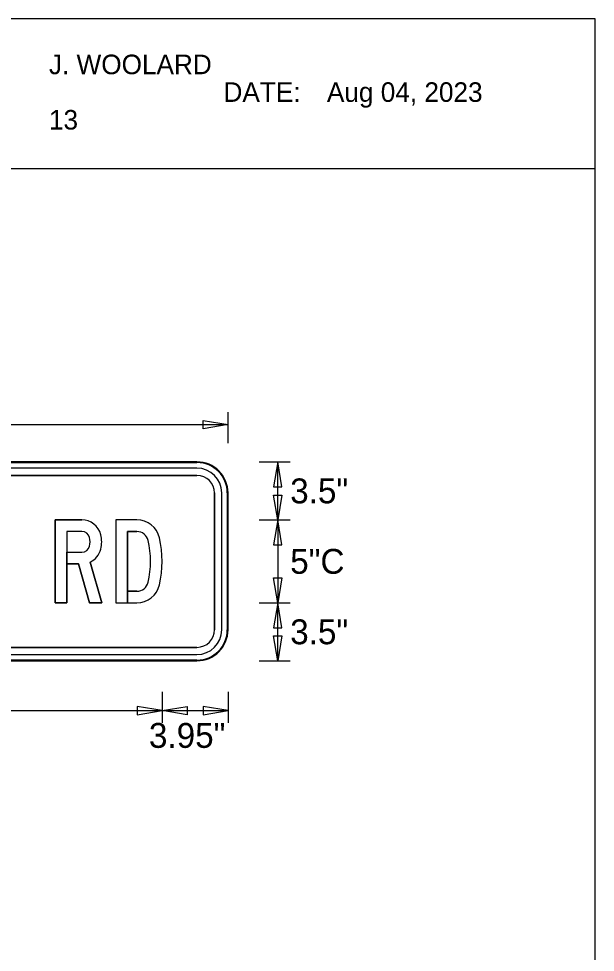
# Model space of a CAD drawing. Extents: x 57.2 to 85.4, y 153.3 to 173.4.
# Drawn here: x 66.811 to 69.711, y 168.405 to 173.098 of the extents above; entities that cross this region are included whole.
import ezdxf

# ---------------------------------------------------------------- set-up
doc = ezdxf.new("R2010")
doc.units = 0
for name, color, linetype in [('Default', 7, 'Continuous'), ('GSBWFILL', 7, 'Continuous'), ('GSCOLORFILL', 7, 'Continuous'), ('GSDIMS', 7, 'Continuous'), ('GSOUTLINE', 7, 'Continuous')]:
    doc.layers.add(name, color=color, linetype=linetype)

msp = doc.modelspace()

# ---------------------------------------------------------------- linework, layer by layer
at = {"layer": 'Default'}
for p, q in [((69.7108, 173.0983), (57.2061, 173.0983)), ((69.7108, 163.7124), (69.7108, 173.0983)), ((63.0173, 172.3449), (69.7108, 172.3449))]:
    msp.add_line(p, q, dxfattribs=at)
at = {"layer": 'GSBWFILL'}
for p, q in [((67.7078, 170.8706), (65.0203, 170.8706)), ((67.7078, 170.8393), (65.0203, 170.8393)), ((65.0203, 170.8028), (67.7078, 170.8028)), ((67.7963, 170.7143), (67.7963, 170.0268)), ((67.8328, 170.0268), (67.8328, 170.7143)), ((67.8641, 170.0268), (67.8641, 170.7143)), ((67.1292, 170.4164), (67.1292, 170.4164)), ((67.4056, 170.2206), (67.3578, 170.2206)), ((67.7078, 169.9383), (65.0207, 169.9383)), ((65.0207, 169.9018), (67.7078, 169.9018)), ((65.0203, 169.8706), (67.7078, 169.8706))]:
    msp.add_line(p, q, dxfattribs=at)
for points in [[(67.1292, 170.5206), (67.0537, 170.5206), (67.0537, 170.1622), (66.9953, 170.1622), (66.9953, 170.5789), (67.1292, 170.5789)], [(67.4056, 170.5789), (67.2995, 170.5789), (67.2995, 170.1622), (67.3578, 170.1622), (67.3578, 170.5206), (67.4056, 170.5206)], [(67.1703, 170.3671), (67.2287, 170.1622), (67.168, 170.1622), (67.1122, 170.3581), (67.0537, 170.3581), (67.0537, 170.4164), (67.1292, 170.4164)], [(67.3578, 170.2206), (67.3578, 170.1622), (67.4056, 170.1622)]]:
    msp.add_lwpolyline(points, dxfattribs=at)
for centre, radius, start, end in [((67.7078, 170.7143), 0.1562, 0, 90), ((67.7078, 170.7143), 0.125, 0, 90), ((67.7078, 170.7143), 0.0885, 0, 90), ((67.7078, 170.0268), 0.125, 270, 0), ((67.7078, 170.0268), 0.0885, 270, 0), ((67.7078, 170.0268), 0.1562, 270, 0)]:
    msp.add_arc(centre, radius, start, end, dxfattribs=at)
for centre, major_axis, start_param, end_param in [((67.1292, 170.481), (0, 0.0979), 4.954755, 6.283185), ((67.4056, 170.4622), (0, 0.1167), 4.941184, 6.283185), ((67.1292, 170.481), (0, 0.0396), 4.954755, 6.283185), ((67.0787, 170.4685), (0, 0.15), 4.470023, 4.954755), ((67.4056, 170.4622), (0, 0.0583), 4.941184, 6.283185), ((67.0787, 170.4685), (0, 0.0917), 4.470023, 4.954755), ((67.012, 170.3706), (0, 0.4625), 4.483594, 4.941184), ((67.012, 170.3706), (0, 0.5208), 4.483594, 4.941184), ((67.1292, 170.456), (0, 0.0396), 3.141593, 4.470023), ((67.1292, 170.456), (0, 0.0979), 3.574819, 4.470023), ((67.4056, 170.2789), (0, 0.0583), 3.141593, 4.483594), ((67.4056, 170.2789), (0, 0.1167), 3.141593, 4.483594)]:
    msp.add_ellipse(centre, major_axis=major_axis, ratio=0.999994, start_param=start_param, end_param=end_param, dxfattribs=at)
at = {"layer": 'GSCOLORFILL'}
for p, q in [((67.7078, 170.8706), (65.0203, 170.8706)), ((67.7078, 170.8706), (65.0203, 170.8706)), ((65.0203, 170.8669), (67.7078, 170.8669)), ((67.7078, 170.8393), (65.0203, 170.8393)), ((65.0203, 170.8028), (67.7078, 170.8028)), ((67.7963, 170.7143), (67.7963, 170.0268)), ((67.8328, 170.0268), (67.8328, 170.7143)), ((67.8604, 170.7143), (67.8604, 170.0268)), ((67.8641, 170.0268), (67.8641, 170.7143)), ((67.8641, 170.0268), (67.8641, 170.7143)), ((67.1292, 170.4164), (67.1292, 170.4164)), ((67.4056, 170.2206), (67.3578, 170.2206)), ((67.7078, 169.9383), (65.0207, 169.9383)), ((65.0207, 169.9018), (67.7078, 169.9018)), ((65.0203, 169.8706), (67.7078, 169.8706)), ((67.7078, 169.8742), (65.0204, 169.8742)), ((65.0204, 169.8706), (67.7078, 169.8706))]:
    msp.add_line(p, q, dxfattribs=at)
for points in [[(67.1292, 170.5206), (67.0537, 170.5206), (67.0537, 170.1622), (66.9953, 170.1622), (66.9953, 170.5789), (67.1292, 170.5789)], [(67.4056, 170.5789), (67.2995, 170.5789), (67.2995, 170.1622), (67.3578, 170.1622), (67.3578, 170.5206), (67.4056, 170.5206)], [(67.1703, 170.3671), (67.2287, 170.1622), (67.168, 170.1622), (67.1122, 170.3581), (67.0537, 170.3581), (67.0537, 170.4164), (67.1292, 170.4164)], [(67.3578, 170.2206), (67.3578, 170.1622), (67.4056, 170.1622)]]:
    msp.add_lwpolyline(points, dxfattribs=at)
for centre, radius, start, end in [((67.7078, 170.7143), 0.1562, 0, 90), ((67.7078, 170.7143), 0.1562, 0, 90), ((67.7078, 170.7143), 0.1526, 0, 90), ((67.7078, 170.7143), 0.125, 0, 90), ((67.7078, 170.7143), 0.0885, 0, 90), ((67.7078, 170.0268), 0.1562, 270, 0), ((67.7078, 170.0268), 0.125, 270, 0), ((67.7078, 170.0268), 0.0885, 270, 0), ((67.7078, 170.0268), 0.1562, 270, 0), ((67.7078, 170.0268), 0.1526, 270, 0)]:
    msp.add_arc(centre, radius, start, end, dxfattribs=at)
for centre, major_axis, start_param, end_param in [((67.1292, 170.481), (0, 0.0979), 4.954755, 6.283185), ((67.4056, 170.4622), (0, 0.1167), 4.941184, 6.283185), ((67.1292, 170.481), (0, 0.0396), 4.954755, 6.283185), ((67.0787, 170.4685), (0, 0.15), 4.470023, 4.954755), ((67.4056, 170.4622), (0, 0.0583), 4.941184, 6.283185), ((67.0787, 170.4685), (0, 0.0917), 4.470023, 4.954755), ((67.012, 170.3706), (0, 0.4625), 4.483594, 4.941184), ((67.012, 170.3706), (0, 0.5208), 4.483594, 4.941184), ((67.1292, 170.456), (0, 0.0396), 3.141593, 4.470023), ((67.1292, 170.456), (0, 0.0979), 3.574819, 4.470023), ((67.4056, 170.2789), (0, 0.0583), 3.141593, 4.483594), ((67.4056, 170.2789), (0, 0.1167), 3.141593, 4.483594)]:
    msp.add_ellipse(centre, major_axis=major_axis, ratio=0.999994, start_param=start_param, end_param=end_param, dxfattribs=at)
at = {"layer": 'GSDIMS'}
for p, q in [((67.8641, 170.9643), (67.8641, 171.1206)), ((64.8641, 171.0581), (67.8641, 171.0581)), ((67.8641, 170.9643), (67.8641, 170.9643)), ((68.0204, 170.8706), (68.1766, 170.8706)), ((68.1141, 170.5789), (68.1141, 170.8706)), ((68.0204, 170.5789), (68.1766, 170.5789)), ((68.0204, 170.5789), (68.1766, 170.5789)), ((68.1141, 170.5789), (68.1141, 170.1622)), ((68.0204, 170.1622), (68.1766, 170.1622)), ((68.0204, 170.1622), (68.1766, 170.1622)), ((68.1141, 169.8706), (68.1141, 170.1622)), ((68.0204, 169.8706), (68.1766, 169.8706)), ((67.5329, 169.7143), (67.5329, 169.5581)), ((67.5329, 169.7143), (67.5329, 169.5581)), ((67.8641, 169.7143), (67.8641, 169.5581)), ((67.8641, 169.7143), (67.8641, 169.5581)), ((65.1953, 169.6206), (67.5329, 169.6206)), ((67.5329, 169.6206), (67.8641, 169.6206))]:
    msp.add_line(p, q, dxfattribs=at)
for points in [[(67.8641, 171.0581), (67.7391, 171.0372), (67.7391, 171.0789)], [(68.1141, 170.8706), (68.0933, 170.7456), (68.1349, 170.7456)], [(68.1141, 170.5789), (68.0933, 170.7039), (68.1349, 170.7039)], [(68.1141, 170.5789), (68.0933, 170.4539), (68.1349, 170.4539)], [(68.1141, 170.1622), (68.0933, 170.2872), (68.1349, 170.2872)], [(68.1141, 170.1622), (68.0933, 170.0372), (68.1349, 170.0372)], [(68.1141, 169.8706), (68.0933, 169.9956), (68.1349, 169.9956)], [(67.5329, 169.6206), (67.4079, 169.6414), (67.4079, 169.5997)], [(67.5329, 169.6206), (67.6579, 169.6414), (67.6579, 169.5997)], [(67.8641, 169.6206), (67.7391, 169.6414), (67.7391, 169.5997)]]:
    msp.add_lwpolyline(points, close=True, dxfattribs=at)
at = {"layer": 'GSOUTLINE'}
for p, q in [((67.7078, 170.8706), (65.0203, 170.8706)), ((67.7078, 170.8393), (65.0203, 170.8393)), ((67.7078, 170.8028), (65.0203, 170.8028)), ((67.7963, 170.0268), (67.7963, 170.7143)), ((67.8328, 170.0268), (67.8328, 170.7143)), ((67.8641, 170.0268), (67.8641, 170.7143)), ((67.1292, 170.5789), (66.9953, 170.5789)), ((67.1292, 170.5206), (67.1292, 170.5206)), ((67.3578, 170.2206), (67.4056, 170.2206)), ((67.4056, 170.1622), (67.4056, 170.1622)), ((65.0203, 169.9383), (67.7078, 169.9383)), ((65.0203, 169.9018), (67.7078, 169.9018)), ((65.0203, 169.8706), (67.7078, 169.8706))]:
    msp.add_line(p, q, dxfattribs=at)
for points in [[(66.9953, 170.5789), (66.9953, 170.1622), (67.0537, 170.1622), (67.0537, 170.3581), (67.1122, 170.3581), (67.168, 170.1622), (67.2287, 170.1622), (67.1703, 170.3671)], [(67.4056, 170.5789), (67.2995, 170.5789), (67.2995, 170.1622), (67.4056, 170.1622)], [(67.1292, 170.5206), (67.0537, 170.5206), (67.0537, 170.4164), (67.1292, 170.4164)], [(67.4056, 170.5206), (67.3578, 170.5206), (67.3578, 170.2206)]]:
    msp.add_lwpolyline(points, dxfattribs=at)
for centre, radius, start, end in [((67.7078, 170.7143), 0.1562, 0, 90), ((67.7078, 170.7143), 0.125, 0, 90), ((67.7078, 170.7143), 0.0885, 0, 90), ((67.7078, 170.0268), 0.125, 270, 0), ((67.7078, 170.0268), 0.0885, 270, 0), ((67.7078, 170.0268), 0.1562, 270, 0)]:
    msp.add_arc(centre, radius, start, end, dxfattribs=at)
for centre, major_axis, start_param, end_param in [((67.1292, 170.481), (0, 0.0979), 4.954755, 6.283185), ((67.4056, 170.4622), (0, 0.1167), 4.941184, 6.283185), ((67.1292, 170.481), (0, 0.0396), 4.954755, 6.283185), ((67.0787, 170.4685), (0, 0.15), 4.470023, 4.954755), ((67.4056, 170.4622), (0, 0.0583), 4.941184, 6.283185), ((67.0787, 170.4685), (0, 0.0917), 4.470023, 4.954755), ((67.012, 170.3706), (0, 0.4625), 4.483594, 4.941184), ((67.012, 170.3706), (0, 0.5208), 4.483594, 4.941184), ((67.1292, 170.456), (0, 0.0396), 3.141593, 4.470023), ((67.1292, 170.456), (0, 0.0979), 3.574819, 4.470023), ((67.4056, 170.2789), (0, 0.0583), 3.141593, 4.483594), ((67.4056, 170.2789), (0, 0.1167), 3.141593, 4.483594)]:
    msp.add_ellipse(centre, major_axis=major_axis, ratio=0.999994, start_param=start_param, end_param=end_param, dxfattribs=at)

# ---------------------------------------------------------------- texts
at = {"layer": 'Default'}
for s, height, p in [('J. WOOLARD', 0.09837, (66.9636, 172.8192)), ('DATE:', 0.09838, (67.8413, 172.6801)), ('Aug 04, 2023', 0.098375, (68.3613, 172.6801)), ('13', 0.09837, (66.9636, 172.541))]:
    msp.add_text(s, height=height, dxfattribs=at).set_placement(p)
at = {"layer": 'GSDIMS'}
for s, p in [('3.5"', (68.1766, 170.6622)), ('5"C', (68.1766, 170.308)), ('3.5"', (68.1766, 169.9539)), ('3.95"', (67.4663, 169.4331))]:
    msp.add_text(s, height=0.125, dxfattribs=at).set_placement(p)

doc.saveas('drawing.dxf')
